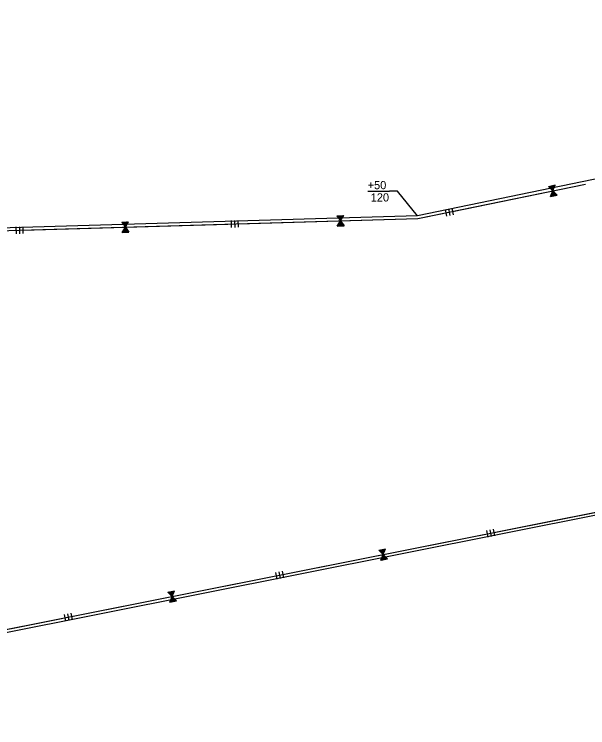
# Model space of a CAD drawing. Extents: x 979729 to 993523, y 1834148 to 1845433.
# Drawn here: x 985517 to 985936, y 1837768 to 1838290 of the extents above; entities that cross this region are included whole.
import ezdxf

# ---------------------------------------------------------------- set-up
doc = ezdxf.new("R2010")
doc.units = 0
for name, color, linetype in [('42', 7, 'Continuous'), ('51', 7, 'Continuous'), ('R_Draft', 7, 'Continuous')]:
    doc.layers.add(name, color=color, linetype=linetype)

msp = doc.modelspace()

# ---------------------------------------------------------------- linework, layer by layer
at = {"layer": '42'}
for p, q in [((985811.99, 1838140.41), (985934.58, 1838165.71)), ((985910.59, 1838161.13), (985912.12, 1838164.91)), ((985910.77, 1838160.89), (985912.41, 1838164.97)), ((985910.82, 1838160.81), (985912.51, 1838164.99)), ((985907.62, 1838163.98), (985910.82, 1838160.81)), ((985907.68, 1838163.94), (985907.71, 1838164)), ((985907.88, 1838163.76), (985908, 1838164.06)), ((985908.07, 1838163.55), (985908.29, 1838164.12)), ((985908.27, 1838163.38), (985908.59, 1838164.18)), ((985908.45, 1838163.17), (985908.88, 1838164.24)), ((985908.64, 1838162.97), (985909.18, 1838164.3)), ((985908.84, 1838162.79), (985909.47, 1838164.36)), ((985909.06, 1838162.68), (985909.7, 1838164.27)), ((985909.13, 1838156.63), (985910.82, 1838160.81)), ((985909.23, 1838162.44), (985910.06, 1838164.48)), ((985909.44, 1838162.27), (985910.36, 1838164.54)), ((985909.61, 1838162.03), (985910.65, 1838164.6)), ((985909.82, 1838161.89), (985910.94, 1838164.66)), ((985910, 1838161.65), (985911.24, 1838164.72)), ((985910.19, 1838161.48), (985911.53, 1838164.79)), ((985910.38, 1838161.27), (985911.83, 1838164.85)), ((985910.4, 1838159.71), (985912.75, 1838157.38)), ((985910.51, 1838159.94), (985913.05, 1838157.44)), ((985910.6, 1838160.21), (985913.34, 1838157.5)), ((985910.74, 1838160.43), (985913.64, 1838157.56)), ((985910.8, 1838160.71), (985913.93, 1838157.62)), ((985910.82, 1838160.81), (985914.03, 1838157.64)), ((985909.18, 1838156.7), (985909.22, 1838156.65)), ((985909.29, 1838156.93), (985909.52, 1838156.71)), ((985909.38, 1838157.2), (985909.81, 1838156.77)), ((985909.5, 1838157.44), (985910.11, 1838156.83)), ((985909.58, 1838157.7), (985910.4, 1838156.89)), ((985909.67, 1838157.96), (985910.69, 1838156.95)), ((985909.79, 1838158.2), (985910.99, 1838157.02)), ((985909.95, 1838158.39), (985911.16, 1838157.19)), ((985910.01, 1838158.68), (985911.58, 1838157.14)), ((985910.13, 1838158.92), (985911.87, 1838157.2)), ((985910.19, 1838159.21), (985912.17, 1838157.26)), ((985910.33, 1838159.42), (985912.46, 1838157.32)), ((985831.97, 1838147.08), (985832.98, 1838142.19)), ((985834.42, 1838147.59), (985835.43, 1838142.69)), ((985836.87, 1838148.09), (985837.88, 1838143.2)), ((985091.38, 1838119.28), (985811.99, 1838140.41)), ((985675.39, 1838138.9), (985675.54, 1838133.9)), ((985677.89, 1838138.98), (985678.04, 1838133.98)), ((985680.39, 1838139.05), (985680.54, 1838134.05)), ((985752.82, 1838142.42), (985755.43, 1838138.75)), ((985752.88, 1838142.37), (985752.91, 1838142.43)), ((985753.05, 1838142.17), (985753.22, 1838142.43)), ((985753.19, 1838141.93), (985753.52, 1838142.44)), ((985753.36, 1838141.73), (985753.82, 1838142.45)), ((985753.51, 1838141.49), (985754.12, 1838142.46)), ((985753.65, 1838141.25), (985754.42, 1838142.47)), ((985753.82, 1838141.05), (985754.72, 1838142.48)), ((985754.02, 1838140.9), (985754.93, 1838142.35)), ((985754.15, 1838140.63), (985755.32, 1838142.5)), ((985754.32, 1838140.42), (985755.62, 1838142.5)), ((985754.45, 1838140.16), (985755.92, 1838142.51)), ((985754.63, 1838139.98), (985756.22, 1838142.52)), ((985754.76, 1838139.72), (985756.52, 1838142.53)), ((985754.93, 1838139.52), (985756.82, 1838142.54)), ((985755.08, 1838139.28), (985757.12, 1838142.55)), ((985755.26, 1838139.1), (985757.42, 1838142.56)), ((985755.39, 1838138.84), (985757.72, 1838142.57)), ((985755.43, 1838138.75), (985757.82, 1838142.57)), ((985517.96, 1838134.29), (985518.11, 1838129.29)), ((985520.46, 1838134.36), (985520.6, 1838129.36)), ((985522.96, 1838134.43), (985523.1, 1838129.43)), ((985595.39, 1838137.81), (985598, 1838134.13)), ((985595.45, 1838137.75), (985595.48, 1838137.81)), ((985595.61, 1838130.31), (985598, 1838134.13)), ((985595.62, 1838137.55), (985595.78, 1838137.82)), ((985595.76, 1838137.31), (985596.08, 1838137.83)), ((985595.93, 1838137.11), (985596.38, 1838137.84)), ((985596.07, 1838136.87), (985596.68, 1838137.85)), ((985596.22, 1838136.63), (985596.98, 1838137.85)), ((985596.39, 1838136.43), (985597.28, 1838137.86)), ((985596.59, 1838136.28), (985597.5, 1838137.73)), ((985596.72, 1838136.01), (985597.89, 1838137.88)), ((985596.89, 1838135.81), (985598.19, 1838137.89)), ((985597.02, 1838135.55), (985598.49, 1838137.9)), ((985597.2, 1838135.37), (985598.79, 1838137.91)), ((985597.33, 1838135.11), (985599.09, 1838137.92)), ((985597.5, 1838134.9), (985599.39, 1838137.92)), ((985597.64, 1838134.66), (985599.69, 1838137.93)), ((985597.67, 1838133.58), (985599.91, 1838130.44)), ((985597.83, 1838134.49), (985599.99, 1838137.94)), ((985597.85, 1838133.77), (985600.21, 1838130.45)), ((985597.96, 1838134.22), (985600.29, 1838137.95)), ((985597.96, 1838134.04), (985600.51, 1838130.45)), ((985598, 1838134.13), (985600.39, 1838137.95)), ((985598, 1838134.13), (985600.61, 1838130.46)), ((985753.04, 1838134.93), (985755.43, 1838138.75)), ((985753.1, 1838134.98), (985753.13, 1838134.93)), ((985753.25, 1838135.2), (985753.44, 1838134.94)), ((985753.38, 1838135.44), (985753.73, 1838134.95)), ((985753.54, 1838135.65), (985754.04, 1838134.96)), ((985753.67, 1838135.9), (985754.34, 1838134.96)), ((985753.8, 1838136.15), (985754.64, 1838134.97)), ((985753.96, 1838136.36), (985754.94, 1838134.98)), ((985754.15, 1838136.52), (985755.14, 1838135.13)), ((985754.26, 1838136.8), (985755.54, 1838135)), ((985754.42, 1838137.01), (985755.84, 1838135.01)), ((985754.53, 1838137.28), (985756.14, 1838135.02)), ((985754.71, 1838137.47), (985756.44, 1838135.03)), ((985754.82, 1838137.74), (985756.74, 1838135.03)), ((985754.98, 1838137.95), (985757.04, 1838135.04)), ((985755.11, 1838138.2), (985757.34, 1838135.05)), ((985755.28, 1838138.39), (985757.64, 1838135.06)), ((985755.39, 1838138.65), (985757.94, 1838135.07)), ((985755.43, 1838138.75), (985758.04, 1838135.07)), ((985595.66, 1838130.37), (985595.7, 1838130.31)), ((985595.82, 1838130.58), (985596, 1838130.32)), ((985595.95, 1838130.83), (985596.3, 1838130.33)), ((985596.11, 1838131.04), (985596.6, 1838130.34)), ((985596.24, 1838131.29), (985596.9, 1838130.35)), ((985596.37, 1838131.53), (985597.2, 1838130.36)), ((985596.53, 1838131.74), (985597.5, 1838130.37)), ((985596.72, 1838131.9), (985597.71, 1838130.51)), ((985596.83, 1838132.18), (985598.1, 1838130.38)), ((985596.99, 1838132.39), (985598.41, 1838130.39)), ((985597.1, 1838132.66), (985598.71, 1838130.4)), ((985597.27, 1838132.85), (985599.01, 1838130.41)), ((985597.39, 1838133.12), (985599.31, 1838130.42)), ((985597.54, 1838133.33), (985599.61, 1838130.43)), ((985159.48, 1837769.83), (985982.51, 1837933.54)), ((985862.21, 1837912.16), (985863.19, 1837907.26)), ((985864.67, 1837912.65), (985865.64, 1837907.75)), ((985867.12, 1837913.14), (985868.09, 1837908.23)), ((985786.46, 1837894.91), (985788.02, 1837898.68)), ((985786.64, 1837894.67), (985788.31, 1837898.74)), ((985786.69, 1837894.59), (985788.41, 1837898.76)), ((985783.51, 1837897.78), (985786.69, 1837894.59)), ((985783.57, 1837897.74), (985783.6, 1837897.8)), ((985783.77, 1837897.57), (985783.89, 1837897.86)), ((985783.96, 1837897.36), (985784.19, 1837897.92)), ((985784.16, 1837897.18), (985784.48, 1837897.98)), ((985784.34, 1837896.97), (985784.78, 1837898.03)), ((985784.52, 1837896.76), (985785.07, 1837898.09)), ((985784.72, 1837896.59), (985785.37, 1837898.15)), ((985784.95, 1837896.48), (985785.6, 1837898.06)), ((985784.97, 1837890.43), (985786.69, 1837894.59)), ((985785.12, 1837896.23), (985785.96, 1837898.27)), ((985785.32, 1837896.06), (985786.25, 1837898.33)), ((985785.49, 1837895.82), (985786.55, 1837898.39)), ((985785.7, 1837895.68), (985786.84, 1837898.44)), ((985785.87, 1837895.44), (985787.14, 1837898.5)), ((985786.07, 1837895.27), (985787.43, 1837898.56)), ((985786.25, 1837895.06), (985787.72, 1837898.62)), ((985786.26, 1837893.49), (985788.6, 1837891.15)), ((985786.38, 1837893.73), (985788.89, 1837891.21)), ((985786.46, 1837893.99), (985789.19, 1837891.26)), ((985786.6, 1837894.21), (985789.48, 1837891.32)), ((985786.67, 1837894.49), (985789.78, 1837891.38)), ((985786.69, 1837894.59), (985789.87, 1837891.4)), ((985785.02, 1837890.49), (985785.06, 1837890.44)), ((985785.13, 1837890.73), (985785.36, 1837890.5)), ((985785.22, 1837890.99), (985785.65, 1837890.56)), ((985785.34, 1837891.23), (985785.95, 1837890.62)), ((985785.43, 1837891.49), (985786.24, 1837890.68)), ((985785.52, 1837891.75), (985786.54, 1837890.74)), ((985785.64, 1837891.99), (985786.83, 1837890.8)), ((985785.8, 1837892.18), (985787.01, 1837890.97)), ((985785.86, 1837892.47), (985787.42, 1837890.91)), ((985785.98, 1837892.71), (985787.72, 1837890.97)), ((985786.05, 1837892.99), (985788.01, 1837891.03)), ((985786.19, 1837893.21), (985788.3, 1837891.09)), ((985707.74, 1837881.44), (985708.72, 1837876.53)), ((985710.19, 1837881.92), (985711.17, 1837877.02)), ((985712.64, 1837882.41), (985713.62, 1837877.51)), ((985630.05, 1837866.04), (985630.6, 1837867.37)), ((985630.25, 1837865.86), (985630.89, 1837867.42)), ((985630.47, 1837865.75), (985631.12, 1837867.33)), ((985630.64, 1837865.51), (985631.48, 1837867.54)), ((985630.84, 1837865.33), (985631.78, 1837867.6)), ((985631.01, 1837865.1), (985632.07, 1837867.66)), ((985631.22, 1837864.95), (985632.37, 1837867.72)), ((985631.4, 1837864.71), (985632.66, 1837867.78)), ((985631.6, 1837864.54), (985632.96, 1837867.83)), ((985631.78, 1837864.33), (985633.25, 1837867.89)), ((985631.99, 1837864.18), (985633.55, 1837867.95)), ((985632.16, 1837863.95), (985633.84, 1837868.01)), ((985632.22, 1837863.86), (985633.94, 1837868.03)), ((985629.03, 1837867.05), (985632.22, 1837863.86)), ((985629.1, 1837867.01), (985629.13, 1837867.07)), ((985629.3, 1837866.84), (985629.42, 1837867.13)), ((985629.48, 1837866.63), (985629.71, 1837867.19)), ((985629.68, 1837866.46), (985630.01, 1837867.25)), ((985629.87, 1837866.25), (985630.3, 1837867.31)), ((985630.5, 1837859.7), (985632.22, 1837863.86)), ((985631.58, 1837862.27), (985633.54, 1837860.3)), ((985631.72, 1837862.48), (985633.83, 1837860.36)), ((985631.78, 1837862.77), (985634.13, 1837860.42)), ((985631.9, 1837863), (985634.42, 1837860.48)), ((985631.99, 1837863.27), (985634.71, 1837860.54)), ((985632.13, 1837863.48), (985635.01, 1837860.6)), ((985632.2, 1837863.77), (985635.3, 1837860.65)), ((985632.22, 1837863.86), (985635.4, 1837860.67)), ((985630.54, 1837859.76), (985630.59, 1837859.72)), ((985630.66, 1837860), (985630.88, 1837859.78)), ((985630.75, 1837860.26), (985631.18, 1837859.83)), ((985630.87, 1837860.5), (985631.47, 1837859.89)), ((985630.96, 1837860.76), (985631.77, 1837859.95)), ((985631.05, 1837861.03), (985632.06, 1837860.01)), ((985631.16, 1837861.26), (985632.36, 1837860.07)), ((985631.33, 1837861.45), (985632.53, 1837860.25)), ((985631.39, 1837861.75), (985632.95, 1837860.19)), ((985631.51, 1837861.98), (985633.24, 1837860.24)), ((985558.17, 1837851.68), (985559.15, 1837846.78)), ((985553.27, 1837850.71), (985554.24, 1837845.81)), ((985555.72, 1837851.2), (985556.69, 1837846.29))]:
    msp.add_line(p, q, dxfattribs=at)
for points in [[(985837.37, 1838145.65), (985934.58, 1838165.71)], [(985907.62, 1838163.98), (985912.51, 1838164.99)], [(985909.13, 1838156.63), (985914.03, 1838157.64)], [(985680.46, 1838136.55), (985811.99, 1838140.41), (985830.03, 1838144.13)], [(985752.82, 1838142.42), (985757.82, 1838142.57)], [(985523.03, 1838131.93), (985672.97, 1838136.33)], [(985595.39, 1838137.81), (985600.39, 1838137.95)], [(985753.04, 1838134.93), (985758.04, 1838135.07)], [(985595.61, 1838130.31), (985600.61, 1838130.46)], [(985867.61, 1837910.69), (985982.51, 1837933.54)], [(985713.13, 1837879.96), (985860.25, 1837909.22)], [(985783.51, 1837897.78), (985788.41, 1837898.76)], [(985784.97, 1837890.43), (985789.87, 1837891.4)], [(985558.66, 1837849.23), (985705.78, 1837878.5)], [(985629.03, 1837867.05), (985633.94, 1837868.03)], [(985630.5, 1837859.7), (985635.4, 1837860.67)], [(985404.19, 1837818.51), (985551.3, 1837847.77)]]:
    msp.add_lwpolyline(points, dxfattribs=at)
at = {"layer": '51'}
msp.add_line((985159.91, 1837767.88), (986515.41, 1838037.5), dxfattribs=at)
msp.add_lwpolyline([(986526.26, 1838289.91), (985811.75, 1838142.4), (985091.14, 1838121.27)], dxfattribs=at)
at = {"layer": 'R_Draft'}
msp.add_line((985775.42, 1838160.41), (985791.22, 1838160.41), dxfattribs=at)
msp.add_lwpolyline([(985811.75, 1838142.4), (985797.22, 1838160.41), (985791.22, 1838160.41)], dxfattribs=at)

# ---------------------------------------------------------------- texts
for s, p in [('+50', (985775.3, 1838161.91)), (' 120', (985775.3, 1838152.91))]:
    msp.add_text(s, height=6, rotation=360, dxfattribs=at).set_placement(p)

doc.saveas('drawing.dxf')
